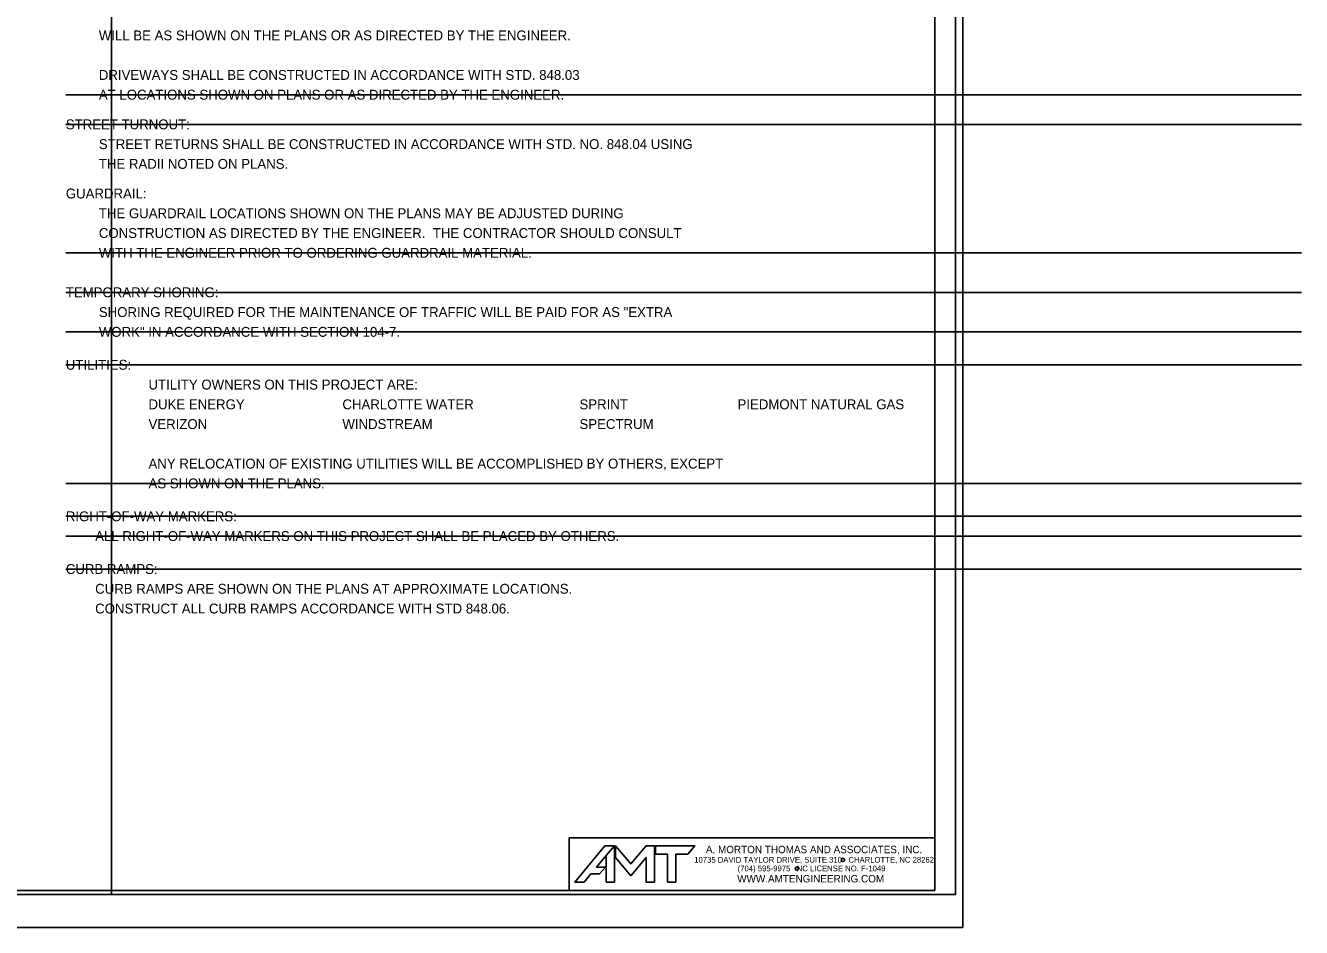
# Model space of a CAD drawing. Extents: x -1492 to 2447, y -56 to 1953.
# Drawn here: x 948 to 1723, y -22 to 525 of the extents above; entities that cross this region are included whole.
import ezdxf

# ---------------------------------------------------------------- set-up
doc = ezdxf.new("R2010")
doc.units = 0
for name, color, linetype in [('Prop Grid Mask', 7, 'Continuous'), ('Scratch_Level_3', 7, 'Continuous'), ('Sheet Block Title CELL', 7, 'Continuous'), ('Sheet Cutting Line CELL', 7, 'Continuous'), ('Sheet Data Text CELL', 7, 'Continuous'), ('Sheet Plan CELL', 7, 'Continuous'), ('Sheet Plot Border Inside CELL', 7, 'Continuous'), ('Sheet Plot Border Outside CELL', 7, 'Continuous')]:
    doc.layers.add(name, color=color, linetype=linetype)

msp = doc.modelspace()

# ---------------------------------------------------------------- linework, layer by layer
at = {"layer": 'Prop Grid Mask'}
msp.add_lwpolyline([(1277.96, 31.96), (1500, 31.95), (1500, 0), (1277.96, 0)], close=True, dxfattribs=at)
at = {"layer": 'Scratch_Level_3'}
for p, q in [((1000, 1050), (1000, -2.5)), ((972.18, 483.15), (1722.72, 483.15)), ((972.18, 465.15), (1722.72, 465.15)), ((972.18, 387.15), (1722.72, 387.15)), ((972.18, 363.15), (1722.72, 363.15)), ((972.18, 339.15), (1722.72, 339.15)), ((972.18, 319.15), (1722.72, 319.15)), ((972.18, 247.15), (1722.72, 247.15)), ((972.18, 227.15), (1722.72, 227.15)), ((972.18, 215.15), (1722.72, 215.15)), ((972.18, 195.15), (1722.72, 195.15))]:
    msp.add_line(p, q, dxfattribs=at)
at = {"layer": 'Sheet Block Title CELL'}
msp.add_lwpolyline([(1277.96, 31.96), (1500, 31.95), (1500, 0), (1277.96, 0)], close=True, dxfattribs=at)
for points in [[(1300.39, 21.1), (1305.42, 27), (1299.54, 27), (1281.32, 5.04), (1287.02, 5.04), (1291.1, 9.98), (1296.32, 9.98), (1299.91, 14.13), (1294.51, 14.13), (1300.39, 21.1)], [(1305.42, 5.04), (1305.42, 27), (1300.39, 21.1), (1300.39, 5.04), (1305.42, 5.04)], [(1315.29, 8.91), (1324.62, 20.03), (1324.62, 5.04), (1329.65, 5.04), (1329.65, 27), (1324.62, 27), (1315.29, 16.04), (1306.07, 27), (1306.07, 20.01), (1315.29, 8.91)], [(1342.68, 5.04), (1342.68, 21.96), (1349.98, 21.96), (1354.19, 27), (1330.3, 27), (1330.3, 21.96), (1337.65, 21.96), (1337.65, 5.04), (1342.68, 5.04)]]:
    msp.add_lwpolyline(points, dxfattribs=at)
for centre in [(1444.19, 18.52), (1416.27, 13.3)]:
    msp.add_circle(centre, 1, dxfattribs=at)
at = {"layer": 'Sheet Cutting Line CELL'}
msp.add_line((-166.5, -22.5), (1517, -22.5), dxfattribs=at)
at = {"layer": 'Sheet Plan CELL'}
msp.add_lwpolyline([(1500, 1050), (0, 1050), (0, 0), (1500, 0)], close=True, dxfattribs=at)
at = {"layer": 'Sheet Plot Border Inside CELL'}
msp.add_lwpolyline([(-153.5, -2.5), (1512.5, -2.5), (1512.5, 1052.5), (-153.5, 1052.5)], close=True, dxfattribs=at)
at = {"layer": 'Sheet Plot Border Outside CELL'}
msp.add_lwpolyline([(-166.5, -22.5), (1517, -22.5), (1517, 1072.5), (-166.5, 1072.5)], close=True, dxfattribs=at)

# ---------------------------------------------------------------- texts
at = {"layer": 'Sheet Block Title CELL'}
for s, height, p in [('A. MORTON THOMAS AND ASSOCIATES, INC.', 4.5, (1360.97, 22.6)), ('10735 DAVID TAYLOR DRIVE, SUITE 310   CHARLOTTE, NC 28262', 3.5, (1353.87, 16.85)), ('WWW.AMTENGINEERING.COM', 4.5, (1379.99, 4.85)), ('(704) 595-9975   NC LICENSE NO. F-1049', 3.5, (1380.26, 11.6))]:
    msp.add_text(s, height=height, rotation=359.99952, dxfattribs=at).set_placement(p)
at = {"layer": 'Sheet Data Text CELL'}
for s, p in [('         WILL BE AS SHOWN ON THE PLANS OR AS DIRECTED BY THE ENGINEER.  ', (972.18, 516.15)), ('         DRIVEWAYS SHALL BE CONSTRUCTED IN ACCORDANCE WITH STD. 848.03', (972.18, 492.15)), ('         AT LOCATIONS SHOWN ON PLANS OR AS DIRECTED BY THE ENGINEER.', (972.18, 480.15)), ('STREET TURNOUT:  ', (972.18, 462.15)), ('         STREET RETURNS SHALL BE CONSTRUCTED IN ACCORDANCE WITH STD. NO. 848.04 USING ', (972.18, 450.15)), ('         THE RADII NOTED ON PLANS.', (972.18, 438.15)), ('GUARDRAIL:  ', (972.18, 420.15)), ('         THE GUARDRAIL LOCATIONS SHOWN ON THE PLANS MAY BE ADJUSTED DURING ', (972.18, 408.15)), ('         CONSTRUCTION AS DIRECTED BY THE ENGINEER.  THE CONTRACTOR SHOULD CONSULT', (972.18, 396.15)), ('         WITH THE ENGINEER PRIOR TO ORDERING GUARDRAIL MATERIAL.', (972.18, 384.15)), ('TEMPORARY SHORING:  ', (972.18, 360.15)), ('         SHORING REQUIRED FOR THE MAINTENANCE OF TRAFFIC WILL BE PAID FOR AS "EXTRA ', (972.18, 348.15)), ('         WORK" IN ACCORDANCE WITH SECTION 104-7.', (972.18, 336.15)), ('UTILITIES:', (972.18, 316.15)), (' UTILITY OWNERS ON THIS PROJECT ARE:', (1020.18, 304.15)), (' DUKE ENERGY', (1020.18, 292.15)), ('CHARLOTTE WATER', (1140.18, 292.15)), ('SPRINT', (1284.17, 292.15)), ('PIEDMONT NATURAL GAS', (1380.17, 292.15)), (' VERIZON', (1020.18, 280.15)), ('WINDSTREAM', (1140.18, 280.15)), ('SPECTRUM', (1284.17, 280.15)), (' ANY RELOCATION OF EXISTING UTILITIES WILL BE ACCOMPLISHED BY OTHERS, EXCEPT', (1020.18, 256.15)), (' AS SHOWN ON THE PLANS.', (1020.18, 244.15)), ('RIGHT-OF-WAY MARKERS:  ', (972.18, 224.15)), ('        ALL RIGHT-OF-WAY MARKERS ON THIS PROJECT SHALL BE PLACED BY OTHERS.', (972.18, 212.15)), ('CURB RAMPS:', (972.18, 192.15)), ('        CURB RAMPS ARE SHOWN ON THE PLANS AT APPROXIMATE LOCATIONS.', (972.18, 180.15)), ('        CONSTRUCT ALL CURB RAMPS ACCORDANCE WITH STD 848.06.', (972.18, 168.15))]:
    msp.add_text(s, height=6, dxfattribs=at).set_placement(p)

doc.saveas('drawing.dxf')
